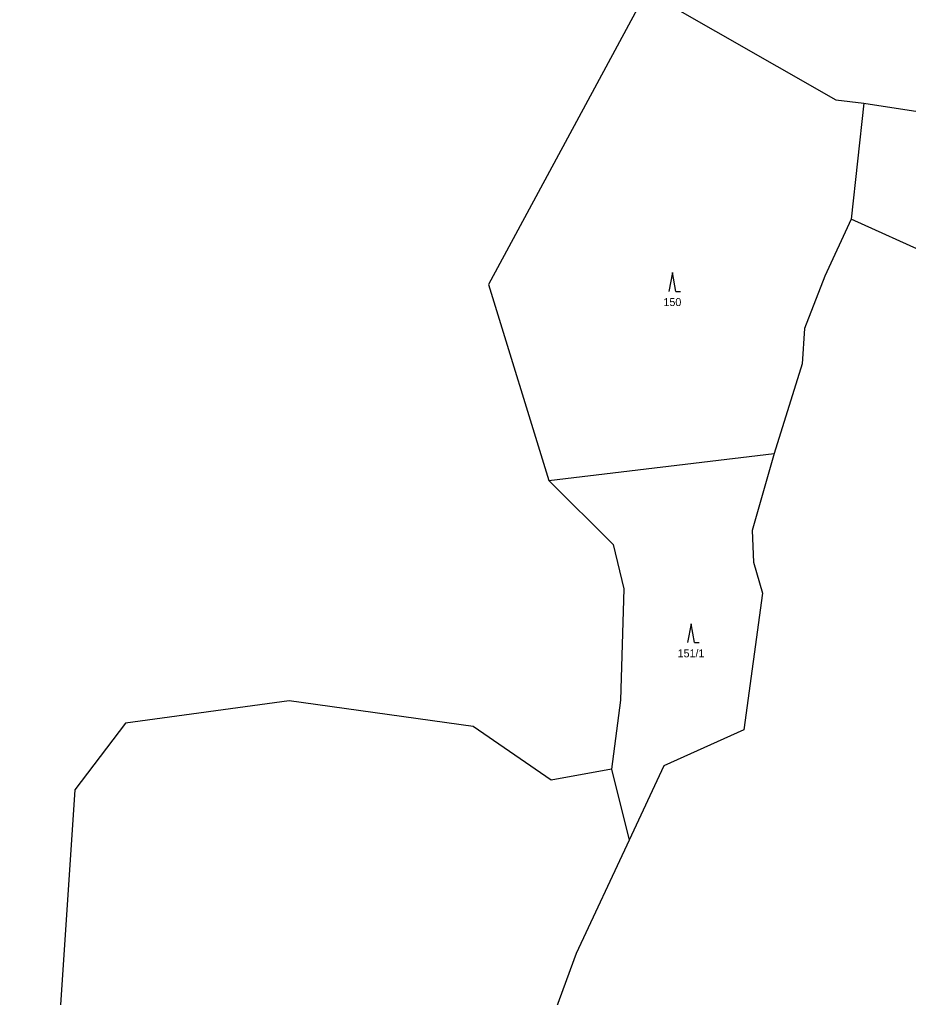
# Model space of a CAD drawing. Extents: x -601877 to -599786, y -1122905 to -1121218.
# Drawn here: x -600816.5 to -600627.6, y -1122443.1 to -1122235.4 of the extents above; entities that cross this region are included whole.
import ezdxf
from ezdxf.enums import TextEntityAlignment as Align

# ---------------------------------------------------------------- set-up
doc = ezdxf.new("R2010")
doc.units = 0
doc.header["$LTSCALE"] = 0.68
doc.layers.add('1', color=7, linetype='Continuous', lineweight=25)
doc.layers.add('3', color=7, linetype='Continuous', lineweight=25)
doc.layers.add('2', color=7, linetype='Continuous')

msp = doc.modelspace()

# ---------------------------------------------------------------- linework, layer by layer
at = {"layer": '1'}
for p, q in [((-600683.28, -1122229.43), (-600643, -1122252.41)), ((-600643, -1122252.41), (-600637.05, -1122253.13)), ((-600637.05, -1122253.13), (-600639.77, -1122277.8)), ((-600637.05, -1122253.13), (-600593.01, -1122260.01)), ((-600639.77, -1122277.8), (-600645.37, -1122289.88)), ((-600608.7, -1122291.84), (-600639.77, -1122277.8)), ((-600645.37, -1122289.88), (-600649.71, -1122300.99)), ((-600716.88, -1122291.68), (-600704.05, -1122333.27)), ((-600649.71, -1122300.99), (-600650.17, -1122308.47)), ((-600650.17, -1122308.47), (-600656.17, -1122327.55)), ((-600704.05, -1122333.27), (-600656.17, -1122327.55)), ((-600656.17, -1122327.55), (-600660.83, -1122343.92)), ((-600704.05, -1122333.27), (-600690.34, -1122346.88)), ((-600660.83, -1122343.92), (-600660.56, -1122350.62)), ((-600660.56, -1122350.62), (-600658.64, -1122357.2)), ((-600658.64, -1122357.2), (-600662.57, -1122386.27)), ((-600759.21, -1122380.1), (-600794, -1122384.82)), ((-600720.08, -1122385.55), (-600759.21, -1122380.1)), ((-600688.79, -1122379.95), (-600690.68, -1122394.59)), ((-600794, -1122384.82), (-600804.79, -1122399.02)), ((-600703.56, -1122396.93), (-600720.08, -1122385.55)), ((-600662.57, -1122386.27), (-600679.6, -1122393.89)), ((-600690.68, -1122394.59), (-600703.56, -1122396.93)), ((-600690.68, -1122394.59), (-600686.93, -1122409.71)), ((-600679.6, -1122393.89), (-600686.93, -1122409.71)), ((-600804.79, -1122399.02), (-600816.51, -1122577.99)), ((-600686.93, -1122409.71), (-600698.25, -1122433.78)), ((-600698.25, -1122433.78), (-600706.41, -1122456.14))]:
    msp.add_line(p, q, dxfattribs=at)
for points in [[(-600727.76, -1122207.35), (-600683.28, -1122229.43), (-600716.88, -1122291.68)], [(-600690.34, -1122346.88), (-600688.06, -1122356.32), (-600688.79, -1122379.95)]]:
    msp.add_lwpolyline(points, dxfattribs=at)
at = {"layer": '3'}
for p, q in [((-600677.02, -1122293.1), (-600676.024, -1122293.1)), ((-600673.06, -1122367.73), (-600672.064, -1122367.73))]:
    msp.add_line(p, q, dxfattribs=at)
for points in [[(-600677.02, -1122293.1), (-600677.77, -1122289.1), (-600678.52, -1122293.1)], [(-600673.06, -1122367.73), (-600673.81, -1122363.73), (-600674.56, -1122367.73)]]:
    msp.add_lwpolyline(points, dxfattribs=at)

# ---------------------------------------------------------------- texts
at = {"layer": '2'}
for s, p in [('150', (-600677.769, -1122296.225)), ('151/1', (-600673.81, -1122370.855))]:
    msp.add_text(s, height=1.7, dxfattribs=at).set_placement(p, align=Align.CENTER)

doc.saveas('drawing.dxf')
